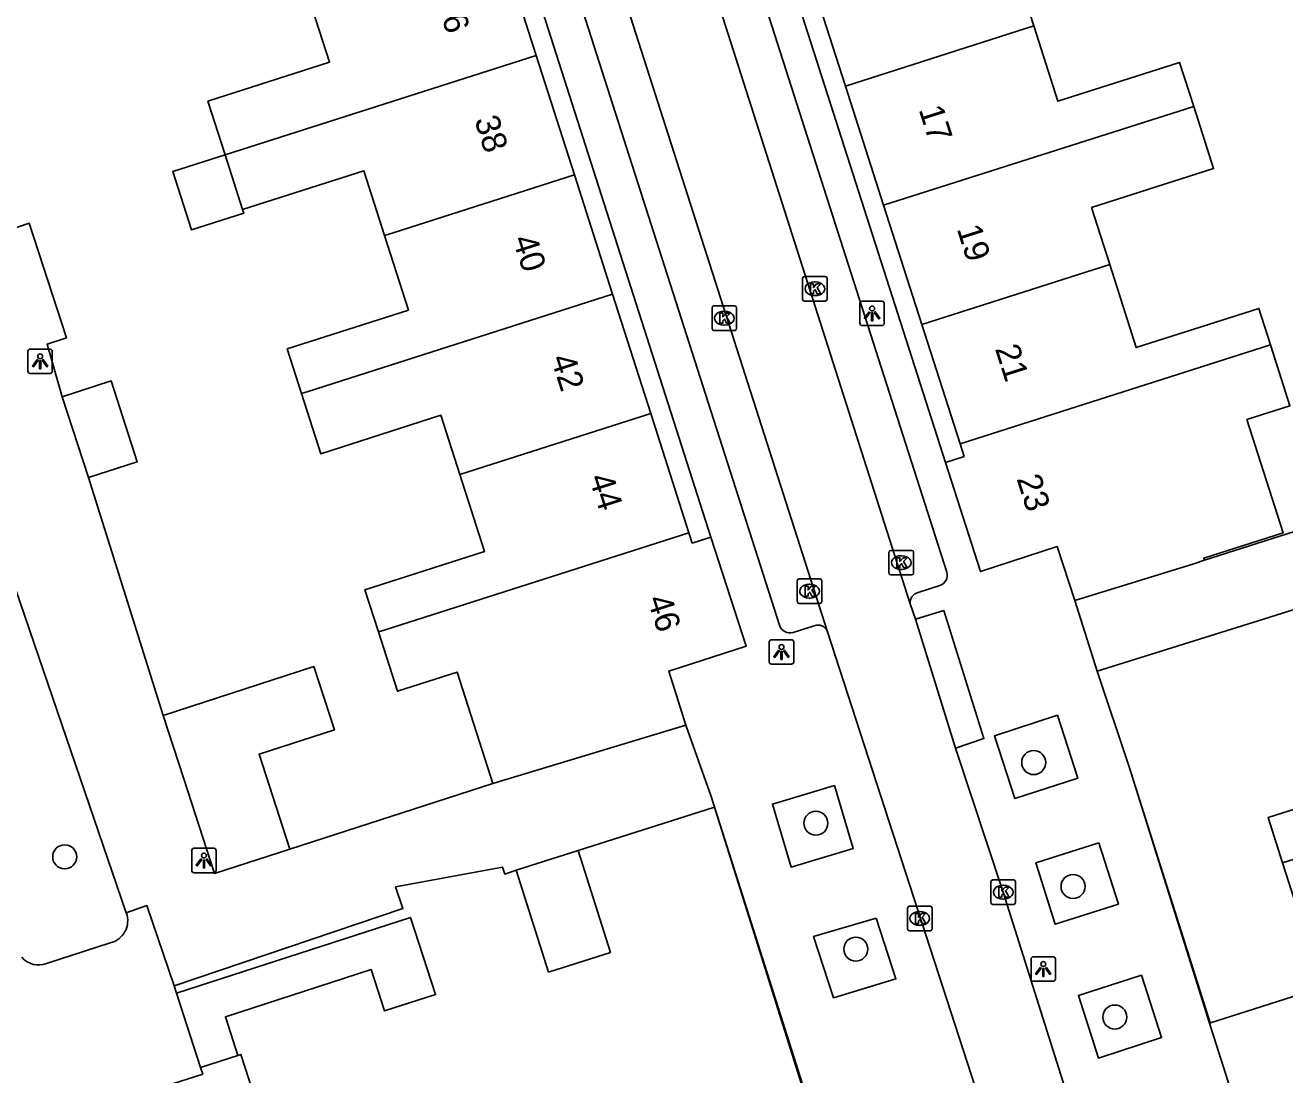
# Model space of a CAD drawing. Extents: x 159718 to 160783, y 383290 to 384030.
# Drawn here: x 160060.5 to 160111.9, y 383577.9 to 383620.7 of the extents above; entities that cross this region are included whole.
import ezdxf

# ---------------------------------------------------------------- set-up
doc = ezdxf.new("R2010")
doc.units = 0
for name, color, linetype in [('IMGEO_Boom', 7, 'Continuous'), ('IMGEO_Kolk', 7, 'Continuous'), ('IMGEO_Lichtpunt', 7, 'Continuous'), ('IMGEO_Muur', 7, 'Continuous'), ('IMGEO_Pand', 7, 'Continuous'), ('IMGEO_Pand_nummerreeks', 7, 'Continuous'), ('IMGEO_Rijbaan_lokaal_open', 7, 'Continuous'), ('IMGEO_Voetpad_open', 7, 'Continuous')]:
    doc.layers.add(name, color=color, linetype=linetype)

msp = doc.modelspace()

# ---------------------------------------------------------------- linework, layer by layer
at = {"layer": 'IMGEO_Boom'}
for centre in [(160101.624, 383590.636), (160092.752, 383588.165), (160062.156, 383586.798), (160103.227, 383585.587), (160094.377, 383583.033), (160104.927, 383580.267)]:
    msp.add_circle(centre, 0.489, dxfattribs=at)
at = {"layer": 'IMGEO_Kolk'}
for p, q in [((160092.21, 383609.519), (160092.21, 383610.371)), ((160092.285, 383610.445), (160093.137, 383610.445)), ((160093.211, 383610.371), (160093.211, 383609.519)), ((160092.698, 383610.225), (160092.723, 383610.225)), ((160093.137, 383609.445), (160092.285, 383609.445)), ((160092.721, 383609.665), (160092.696, 383609.665)), ((160088.522, 383608.32), (160088.522, 383609.172)), ((160088.597, 383609.246), (160089.449, 383609.246)), ((160089.01, 383609.026), (160089.035, 383609.026)), ((160089.523, 383609.172), (160089.523, 383608.32)), ((160089.449, 383608.246), (160088.597, 383608.246)), ((160089.033, 383608.466), (160089.008, 383608.466)), ((160095.73, 383598.359), (160095.73, 383599.211)), ((160095.805, 383599.285), (160096.657, 383599.285)), ((160096.218, 383599.065), (160096.243, 383599.065)), ((160096.731, 383599.211), (160096.731, 383598.359)), ((160096.241, 383598.505), (160096.216, 383598.505)), ((160091.992, 383597.196), (160091.992, 383598.048)), ((160092.067, 383598.122), (160092.919, 383598.122)), ((160092.993, 383598.048), (160092.993, 383597.196)), ((160096.657, 383598.285), (160095.805, 383598.285)), ((160092.48, 383597.902), (160092.505, 383597.902)), ((160092.919, 383597.122), (160092.067, 383597.122)), ((160092.503, 383597.342), (160092.478, 383597.342)), ((160099.883, 383584.928), (160099.883, 383585.78)), ((160099.958, 383585.854), (160100.81, 383585.854)), ((160100.884, 383585.78), (160100.884, 383584.928)), ((160100.371, 383585.634), (160100.396, 383585.634)), ((160096.483, 383583.857), (160096.483, 383584.709)), ((160096.558, 383584.783), (160097.41, 383584.783)), ((160097.484, 383584.709), (160097.484, 383583.857)), ((160100.81, 383584.854), (160099.958, 383584.854)), ((160100.394, 383585.074), (160100.369, 383585.074)), ((160096.971, 383584.563), (160096.996, 383584.563)), ((160097.41, 383583.783), (160096.558, 383583.783)), ((160096.994, 383584.003), (160096.969, 383584.003))]:
    msp.add_line(p, q, dxfattribs=at)
for points in [[(160092.21, 383609.519), (160092.21, 383610.371)], [(160092.285, 383610.445), (160093.137, 383610.445)], [(160093.211, 383610.371), (160093.211, 383609.519)], [(160092.531, 383610.145), (160092.654, 383610.145), (160092.654, 383609.994), (160092.784, 383610.145), (160092.948, 383610.145), (160092.802, 383609.994), (160092.955, 383609.745), (160092.803, 383609.745), (160092.718, 383609.909), (160092.654, 383609.842), (160092.654, 383609.745), (160092.531, 383609.745), (160092.531, 383610.145)], [(160093.137, 383609.445), (160092.285, 383609.445)], [(160088.522, 383608.32), (160088.522, 383609.172)], [(160088.597, 383609.246), (160089.449, 383609.246)], [(160088.843, 383608.946), (160088.966, 383608.946), (160088.966, 383608.795), (160089.096, 383608.946), (160089.26, 383608.946), (160089.114, 383608.795), (160089.267, 383608.546), (160089.115, 383608.546), (160089.03, 383608.71), (160088.966, 383608.643), (160088.966, 383608.546), (160088.843, 383608.546), (160088.843, 383608.946)], [(160089.523, 383609.172), (160089.523, 383608.32)], [(160089.449, 383608.246), (160088.597, 383608.246)], [(160095.73, 383598.359), (160095.73, 383599.211)], [(160095.805, 383599.285), (160096.657, 383599.285)], [(160096.731, 383599.211), (160096.731, 383598.359)], [(160096.051, 383598.985), (160096.174, 383598.985), (160096.174, 383598.834), (160096.304, 383598.985), (160096.468, 383598.985), (160096.322, 383598.834), (160096.475, 383598.585), (160096.323, 383598.585), (160096.238, 383598.749), (160096.174, 383598.682), (160096.174, 383598.585), (160096.051, 383598.585), (160096.051, 383598.985)], [(160091.992, 383597.196), (160091.992, 383598.048)], [(160092.067, 383598.122), (160092.919, 383598.122)], [(160092.993, 383598.048), (160092.993, 383597.196)], [(160096.657, 383598.285), (160095.805, 383598.285)], [(160092.313, 383597.822), (160092.436, 383597.822), (160092.436, 383597.671), (160092.566, 383597.822), (160092.73, 383597.822), (160092.584, 383597.671), (160092.737, 383597.422), (160092.585, 383597.422), (160092.5, 383597.586), (160092.436, 383597.519), (160092.436, 383597.422), (160092.313, 383597.422), (160092.313, 383597.822)], [(160092.919, 383597.122), (160092.067, 383597.122)], [(160099.883, 383584.928), (160099.883, 383585.78)], [(160099.958, 383585.854), (160100.81, 383585.854)], [(160100.884, 383585.78), (160100.884, 383584.928)], [(160100.204, 383585.554), (160100.327, 383585.554), (160100.327, 383585.403), (160100.457, 383585.554), (160100.621, 383585.554), (160100.475, 383585.403), (160100.628, 383585.154), (160100.476, 383585.154), (160100.391, 383585.318), (160100.327, 383585.251), (160100.327, 383585.154), (160100.204, 383585.154), (160100.204, 383585.554)], [(160096.483, 383583.857), (160096.483, 383584.709)], [(160096.558, 383584.783), (160097.41, 383584.783)], [(160097.484, 383584.709), (160097.484, 383583.857)], [(160100.81, 383584.854), (160099.958, 383584.854)], [(160096.804, 383584.483), (160096.927, 383584.483), (160096.927, 383584.332), (160097.057, 383584.483), (160097.221, 383584.483), (160097.075, 383584.332), (160097.228, 383584.083), (160097.076, 383584.083), (160096.991, 383584.247), (160096.927, 383584.18), (160096.927, 383584.083), (160096.804, 383584.083), (160096.804, 383584.483)], [(160097.41, 383583.783), (160096.558, 383583.783)]]:
    msp.add_lwpolyline(points, dxfattribs=at)
for centre, start, end in [((160092.287, 383610.369), 91.552, 178.448), ((160092.287, 383610.369), 91.552, 178.448), ((160093.135, 383610.369), 1.552, 88.448), ((160093.135, 383610.369), 1.552, 88.448), ((160092.287, 383609.521), 181.552, 268.448), ((160092.287, 383609.521), 181.552, 268.448), ((160093.135, 383609.521), 271.552, 358.448), ((160093.135, 383609.521), 271.552, 358.448), ((160088.599, 383609.17), 91.552, 178.448), ((160088.599, 383609.17), 91.552, 178.448), ((160089.447, 383609.17), 1.552, 88.448), ((160089.447, 383609.17), 1.552, 88.448), ((160088.599, 383608.322), 181.552, 268.448), ((160088.599, 383608.322), 181.552, 268.448), ((160089.447, 383608.322), 271.552, 358.448), ((160089.447, 383608.322), 271.552, 358.448), ((160095.807, 383599.209), 91.552, 178.448), ((160095.807, 383599.209), 91.552, 178.448), ((160096.655, 383599.209), 1.552, 88.448), ((160096.655, 383599.209), 1.552, 88.448), ((160092.069, 383598.046), 91.552, 178.448), ((160092.069, 383598.046), 91.552, 178.448), ((160092.917, 383598.046), 1.552, 88.448), ((160092.917, 383598.046), 1.552, 88.448), ((160095.807, 383598.361), 181.552, 268.448), ((160095.807, 383598.361), 181.552, 268.448), ((160096.655, 383598.361), 271.552, 358.448), ((160096.655, 383598.361), 271.552, 358.448), ((160092.069, 383597.198), 181.552, 268.448), ((160092.069, 383597.198), 181.552, 268.448), ((160092.917, 383597.198), 271.552, 358.448), ((160092.917, 383597.198), 271.552, 358.448), ((160099.96, 383585.778), 91.552, 178.448), ((160099.96, 383585.778), 91.552, 178.448), ((160100.808, 383585.778), 1.552, 88.448), ((160100.808, 383585.778), 1.552, 88.448), ((160096.56, 383584.707), 91.552, 178.448), ((160096.56, 383584.707), 91.552, 178.448), ((160097.408, 383584.707), 1.552, 88.448), ((160097.408, 383584.707), 1.552, 88.448), ((160099.96, 383584.93), 181.552, 268.448), ((160099.96, 383584.93), 181.552, 268.448), ((160100.808, 383584.93), 271.552, 358.448), ((160100.808, 383584.93), 271.552, 358.448), ((160096.56, 383583.859), 181.552, 268.448), ((160096.56, 383583.859), 181.552, 268.448), ((160097.408, 383583.859), 271.552, 358.448), ((160097.408, 383583.859), 271.552, 358.448)]:
    msp.add_arc(centre, 0.0765, start, end, dxfattribs=at)
for centre, major_axis, ratio, start_param, end_param in [((160092.697, 383609.945), (-0.387, 0.002), 0.722429, 4.712389, 7.853982), ((160092.722, 383609.945), (-0.39, 0.002), 0.717154, 1.570796, 4.712389), ((160089.009, 383608.746), (-0.387, 0.002), 0.722429, 4.712389, 7.853982), ((160089.034, 383608.746), (-0.39, 0.002), 0.717154, 1.570796, 4.712389), ((160096.217, 383598.785), (-0.387, 0.002), 0.722429, 4.712389, 7.853982), ((160096.242, 383598.785), (-0.39, 0.002), 0.717154, 1.570796, 4.712389), ((160092.479, 383597.622), (-0.387, 0.002), 0.722429, 4.712389, 7.853982), ((160092.504, 383597.622), (-0.39, 0.002), 0.717154, 1.570796, 4.712389), ((160100.37, 383585.354), (-0.387, 0.002), 0.722429, 4.712389, 7.853982), ((160100.395, 383585.354), (-0.39, 0.002), 0.717154, 1.570796, 4.712389), ((160096.97, 383584.283), (-0.387, 0.002), 0.722429, 4.712389, 7.853982), ((160096.995, 383584.283), (-0.39, 0.002), 0.717154, 1.570796, 4.712389)]:
    msp.add_ellipse(centre, major_axis=major_axis, ratio=ratio, start_param=start_param, end_param=end_param, dxfattribs=at)
at = {"layer": 'IMGEO_Lichtpunt'}
for p, q in [((160094.543, 383609.344), (160094.543, 383608.537)), ((160094.543, 383609.344), (160094.543, 383608.537)), ((160095.445, 383609.439), (160094.637, 383609.439)), ((160095.445, 383609.439), (160094.637, 383609.439)), ((160095.539, 383608.537), (160095.539, 383609.344)), ((160095.539, 383608.537), (160095.539, 383609.344)), ((160094.637, 383608.443), (160095.445, 383608.443)), ((160094.637, 383608.443), (160095.445, 383608.443)), ((160060.656, 383607.395), (160060.656, 383606.588)), ((160060.656, 383607.395), (160060.656, 383606.588)), ((160061.558, 383607.49), (160060.75, 383607.49)), ((160061.558, 383607.49), (160060.75, 383607.49)), ((160061.652, 383606.588), (160061.652, 383607.395)), ((160061.652, 383606.588), (160061.652, 383607.395)), ((160060.75, 383606.494), (160061.558, 383606.494)), ((160060.75, 383606.494), (160061.558, 383606.494)), ((160090.852, 383595.548), (160090.852, 383594.741)), ((160090.852, 383595.548), (160090.852, 383594.741)), ((160091.754, 383595.643), (160090.946, 383595.643)), ((160091.754, 383595.643), (160090.946, 383595.643)), ((160091.848, 383594.741), (160091.848, 383595.548)), ((160091.848, 383594.741), (160091.848, 383595.548)), ((160090.946, 383594.647), (160091.754, 383594.647)), ((160090.946, 383594.647), (160091.754, 383594.647)), ((160067.328, 383587.049), (160067.328, 383586.242)), ((160067.328, 383587.049), (160067.328, 383586.242)), ((160068.23, 383587.144), (160067.422, 383587.144)), ((160068.23, 383587.144), (160067.422, 383587.144)), ((160068.324, 383586.242), (160068.324, 383587.049)), ((160068.324, 383586.242), (160068.324, 383587.049)), ((160067.422, 383586.148), (160068.23, 383586.148)), ((160067.422, 383586.148), (160068.23, 383586.148)), ((160101.515, 383582.627), (160101.515, 383581.82)), ((160101.515, 383582.627), (160101.515, 383581.82)), ((160102.417, 383582.722), (160101.609, 383582.722)), ((160102.417, 383582.722), (160101.609, 383582.722)), ((160102.511, 383581.82), (160102.511, 383582.627)), ((160102.511, 383581.82), (160102.511, 383582.627)), ((160101.609, 383581.726), (160102.417, 383581.726)), ((160101.609, 383581.726), (160102.417, 383581.726))]:
    msp.add_line(p, q, dxfattribs=at)
for points in [[(160094.917, 383609.008), (160094.956, 383608.98), (160094.768, 383608.718), (160094.73, 383608.745), (160094.917, 383609.008)], [(160095.019, 383608.96), (160095.066, 383608.96), (160095.066, 383608.638), (160095.019, 383608.638), (160095.019, 383608.96)], [(160095.129, 383608.98), (160095.167, 383609.007), (160095.354, 383608.745), (160095.315, 383608.717), (160095.129, 383608.98)], [(160061.03, 383607.059), (160061.069, 383607.031), (160060.881, 383606.769), (160060.843, 383606.796), (160061.03, 383607.059)], [(160061.132, 383607.011), (160061.179, 383607.011), (160061.179, 383606.689), (160061.132, 383606.689), (160061.132, 383607.011)], [(160061.242, 383607.031), (160061.28, 383607.058), (160061.467, 383606.796), (160061.428, 383606.768), (160061.242, 383607.031)], [(160091.226, 383595.212), (160091.265, 383595.184), (160091.077, 383594.922), (160091.039, 383594.949), (160091.226, 383595.212)], [(160091.328, 383595.164), (160091.375, 383595.164), (160091.375, 383594.842), (160091.328, 383594.842), (160091.328, 383595.164)], [(160091.438, 383595.184), (160091.476, 383595.211), (160091.663, 383594.949), (160091.624, 383594.921), (160091.438, 383595.184)], [(160067.702, 383586.713), (160067.741, 383586.685), (160067.553, 383586.423), (160067.515, 383586.45), (160067.702, 383586.713)], [(160067.914, 383586.685), (160067.952, 383586.712), (160068.139, 383586.45), (160068.1, 383586.422), (160067.914, 383586.685)], [(160067.804, 383586.665), (160067.851, 383586.665), (160067.851, 383586.343), (160067.804, 383586.343), (160067.804, 383586.665)], [(160101.889, 383582.291), (160101.928, 383582.263), (160101.74, 383582.001), (160101.702, 383582.028), (160101.889, 383582.291)], [(160101.991, 383582.243), (160102.038, 383582.243), (160102.038, 383581.921), (160101.991, 383581.921), (160101.991, 383582.243)], [(160102.101, 383582.263), (160102.139, 383582.29), (160102.326, 383582.028), (160102.287, 383582), (160102.101, 383582.263)]]:
    msp.add_lwpolyline(points, dxfattribs=at)
for centre in [(160095.042, 383609.142), (160061.155, 383607.193), (160091.351, 383595.346), (160067.827, 383586.847), (160102.014, 383582.425)]:
    msp.add_circle(centre, 0.0994, dxfattribs=at)
for centre, start, end in [((160094.637, 383609.344), 90, 180), ((160094.637, 383609.344), 90, 180), ((160095.445, 383609.344), 0, 90), ((160095.445, 383609.344), 0, 90), ((160094.637, 383608.537), 180, 270), ((160094.637, 383608.537), 180, 270), ((160095.445, 383608.537), 270, 0), ((160095.445, 383608.537), 270, 360), ((160060.75, 383607.395), 90, 180), ((160060.75, 383607.395), 90, 180), ((160061.558, 383607.395), 0, 90), ((160061.558, 383607.395), 0, 90), ((160060.75, 383606.588), 180, 270), ((160060.75, 383606.588), 180, 270), ((160061.558, 383606.588), 270, 0), ((160061.558, 383606.588), 270, 360), ((160090.946, 383595.548), 90, 180), ((160090.946, 383595.548), 90, 180), ((160091.754, 383595.548), 0, 90), ((160091.754, 383595.548), 0, 90), ((160090.946, 383594.741), 180, 270), ((160090.946, 383594.741), 180, 270), ((160091.754, 383594.741), 270, 0), ((160091.754, 383594.741), 270, 360), ((160067.422, 383587.049), 90, 180), ((160067.422, 383587.049), 90, 180), ((160068.23, 383587.049), 0, 90), ((160068.23, 383587.049), 0, 90), ((160067.422, 383586.242), 180, 270), ((160067.422, 383586.242), 180, 270), ((160068.23, 383586.242), 270, 0), ((160068.23, 383586.242), 270, 360), ((160101.609, 383582.627), 90, 180), ((160101.609, 383582.627), 90, 180), ((160102.417, 383582.627), 0, 90), ((160102.417, 383582.627), 0, 90), ((160101.609, 383581.82), 180, 270), ((160101.609, 383581.82), 180, 270), ((160102.417, 383581.82), 270, 0), ((160102.417, 383581.82), 270, 360)]:
    msp.add_arc(centre, 0.0946, start, end, dxfattribs=at)
at = {"layer": 'IMGEO_Muur'}
for points in [[(160108.81, 383580.026), (160105.518, 383590.459)], [(160093.03, 383574.919), (160088.483, 383589.256)]]:
    msp.add_lwpolyline(points, dxfattribs=at)
at = {"layer": 'IMGEO_Pand'}
for points in [[(160101.626, 383620.655), (160100.765, 383623.356), (160105.761, 383624.949), (160105.071, 383627.111)], [(160081.362, 383619.454), (160079.807, 383624.317)], [(160092.396, 383623.068), (160093.953, 383618.208)], [(160068.687, 383615.399), (160067.986, 383617.59), (160072.943, 383619.176), (160072.088, 383621.848)], [(160093.953, 383618.208), (160101.626, 383620.655)], [(160108.141, 383617.377), (160107.568, 383619.172), (160102.604, 383617.589), (160101.626, 383620.655)], [(160081.362, 383619.454), (160068.687, 383615.399)], [(160082.917, 383614.592), (160081.362, 383619.454)], [(160093.953, 383618.208), (160095.51, 383613.348)], [(160108.141, 383617.377), (160095.51, 383613.348)], [(160104.722, 383610.928), (160103.979, 383613.257), (160108.949, 383614.842), (160108.141, 383617.377)], [(160069.399, 383613.174), (160069.447, 383613.024), (160067.317, 383612.342), (160066.557, 383614.718), (160068.687, 383615.399)], [(160068.687, 383615.399), (160069.399, 383613.174)], [(160069.399, 383613.174), (160074.338, 383614.754), (160075.182, 383612.117)], [(160075.182, 383612.117), (160075.538, 383612.231), (160082.917, 383614.592)], [(160084.471, 383609.73), (160082.917, 383614.592)], [(160095.51, 383613.348), (160097.067, 383608.487)], [(160075.182, 383612.117), (160076.154, 383609.079), (160071.22, 383607.5), (160071.803, 383605.677)], [(160097.067, 383608.487), (160104.722, 383610.928)], [(160111.27, 383607.66), (160110.797, 383609.145), (160105.799, 383607.551), (160104.722, 383610.928)], [(160084.471, 383609.73), (160072.069, 383605.762), (160071.803, 383605.677)], [(160086.026, 383604.867), (160084.471, 383609.73)], [(160097.067, 383608.487), (160098.624, 383603.627)], [(160098.624, 383603.627), (160111.27, 383607.66)], [(160108.575, 383598.879), (160108.547, 383598.968), (160111.782, 383600), (160110.311, 383604.614), (160112.063, 383605.173), (160111.27, 383607.66)], [(160062.055, 383605.547), (160064.047, 383606.191), (160065.113, 383602.894), (160063.121, 383602.25)], [(160071.803, 383605.677), (160072.587, 383603.224), (160077.482, 383604.79), (160078.253, 383602.38)], [(160063.121, 383602.25), (160062.055, 383605.547)], [(160078.253, 383602.38), (160078.593, 383602.489), (160086.026, 383604.867)], [(160087.582, 383600.004), (160086.026, 383604.867)], [(160098.624, 383603.627), (160098.789, 383603.111), (160098.028, 383602.867)], [(160098.028, 383602.867), (160099.456, 383598.422), (160102.586, 383599.437), (160103.294, 383597.238)], [(160074.935, 383595.959), (160074.385, 383597.68), (160079.258, 383599.239), (160078.253, 383602.38)], [(160087.582, 383600.004), (160075.169, 383596.034), (160074.935, 383595.959)], [(160088.478, 383599.828), (160089.909, 383595.376), (160086.757, 383594.365), (160087.46, 383592.162)], [(160088.478, 383599.828), (160087.716, 383599.583), (160087.582, 383600.004)], [(160108.575, 383598.879), (160108.146, 383598.742), (160103.294, 383597.238)], [(160079.595, 383589.79), (160078.145, 383594.326), (160075.707, 383593.546), (160074.935, 383595.959)], [(160066.171, 383592.559), (160072.307, 383594.545), (160073.142, 383591.966), (160070.074, 383590.973), (160071.326, 383587.105)], [(160071.326, 383587.105), (160068.258, 383586.111), (160067.006, 383589.979), (160066.171, 383592.559)], [(160087.46, 383592.162), (160079.595, 383589.79)], [(160111.764, 383586.547), (160111.173, 383588.394), (160113.104, 383589.012), (160113.694, 383587.165)], [(160080.549, 383586.253), (160083.064, 383587.057)], [(160083.064, 383587.057), (160084.382, 383582.901), (160081.867, 383582.097), (160080.549, 383586.253)], [(160113.694, 383587.165), (160111.764, 383586.547)], [(160108.784, 383580.014), (160113.382, 383581.489), (160111.764, 383586.547)], [(160066.713, 383581.238), (160076.247, 383584.326), (160077.263, 383581.188), (160075.18, 383580.514), (160074.634, 383582.2), (160068.702, 383580.28), (160069.212, 383578.705)], [(160066.713, 383581.238), (160067.693, 383578.213)], [(160108.784, 383580.014), (160110.383, 383574.974)], [(160067.693, 383578.213), (160069.212, 383578.705)], [(160069.212, 383578.705), (160069.327, 383578.742), (160072.068, 383570.277), (160070.582, 383569.796)], [(160067.693, 383578.213), (160067.782, 383577.939), (160066.245, 383577.442)]]:
    msp.add_lwpolyline(points, dxfattribs=at)
at = {"layer": 'IMGEO_Rijbaan_lokaal_open'}
for points in [[(160096.587, 383597.112), (160087.826, 383624.591)], [(160084.42, 383623.496), (160093.206, 383595.999)], [(160096.587, 383597.112), (160096.806, 383596.486)], [(160098.433, 383591.22), (160096.806, 383596.486)], [(160100.43, 383573.741), (160093.206, 383595.999)], [(160098.433, 383591.22), (160100.384, 383585.354), (160104.021, 383573.815)]]:
    msp.add_lwpolyline(points, dxfattribs=at)
at = {"layer": 'IMGEO_Voetpad_open'}
for points in [[(160079.624, 383656.083), (160098.092, 383598.396)], [(160091.264, 383596.231), (160072.804, 383653.926)], [(160082.144, 383652.447), (160098.028, 383602.867)], [(160072.621, 383649.414), (160088.478, 383599.828)], [(160104.211, 383594.364), (160110.764, 383596.41), (160127.456, 383601.679), (160120.476, 383623.696), (160119.09, 383628.068), (160113.81, 383644.725), (160123.842, 383647.93)], [(160115.198, 383635.752), (160121.604, 383615.913), (160125.373, 383604.243), (160108.575, 383598.879)], [(160062.055, 383605.547), (160061.437, 383607.691), (160062.226, 383607.946), (160060.714, 383612.62), (160059.874, 383612.332)], [(160056.648, 383611.226), (160055.644, 383610.877), (160064.665, 383584.508)], [(160066.171, 383592.559), (160063.121, 383602.25)], [(160097.796, 383597.855), (160096.924, 383597.571)], [(160103.294, 383597.238), (160104.211, 383594.364)], [(160096.806, 383596.486), (160097.962, 383596.832), (160099.593, 383591.624), (160098.433, 383591.22)], [(160092.689, 383596.206), (160091.827, 383595.933)], [(160104.211, 383594.364), (160105.518, 383590.459), (160108.784, 383580.014)], [(160102.599, 383592.562), (160103.427, 383590.003), (160100.858, 383589.172), (160100.03, 383591.731), (160102.599, 383592.562)], [(160087.46, 383592.162), (160088.483, 383589.256), (160088.621, 383588.82)], [(160079.595, 383589.79), (160071.326, 383587.105)], [(160093.506, 383589.699), (160094.272, 383587.135), (160091.746, 383586.38), (160090.98, 383588.944), (160093.506, 383589.699)], [(160083.064, 383587.057), (160088.621, 383588.82)], [(160088.621, 383588.82), (160092.964, 383574.977)], [(160104.283, 383587.369), (160105.075, 383584.861), (160102.501, 383584.048), (160101.708, 383586.556), (160104.283, 383587.369)], [(160066.615, 383581.531), (160075.935, 383584.689), (160075.634, 383585.576), (160079.988, 383586.376), (160080.083, 383586.095), (160080.549, 383586.253)], [(160064.665, 383584.508), (160065.501, 383584.818), (160066.615, 383581.531)], [(160095.202, 383584.296), (160096.013, 383581.82), (160093.463, 383581.051), (160092.658, 383583.548), (160095.202, 383584.296)], [(160064.009, 383583.284), (160061.419, 383582.447)], [(160106.01, 383581.974), (160106.836, 383579.429), (160104.268, 383578.595), (160103.442, 383581.139), (160106.01, 383581.974)], [(160066.615, 383581.531), (160066.713, 383581.238)]]:
    msp.add_lwpolyline(points, dxfattribs=at)
for centre, radius, start, end in [((160097.66, 383598.281), 0.447, 287.7226, 14.9082), ((160097.039, 383597.134), 0.452, 104.6832, 182.7442), ((160091.711, 383596.394), 0.476, 200.0787, 284.1361), ((160092.849, 383595.856), 0.385, 21.8561, 114.5029), ((160063.794, 383584.187), 0.928, 283.378, 20.2441), ((160061.095, 383583.285), 0.899, 220.4555, 291.1513)]:
    msp.add_arc(centre, radius, start, end, dxfattribs=at)

# ---------------------------------------------------------------- texts
at = {"layer": 'IMGEO_Pand_nummerreeks'}
for s, rotation, p in [('36', 287.7386, (160077.278, 383621.694)), ('38', 287.7386, (160078.834, 383616.829)), ('17', 287.687, (160096.934, 383617.253)), ('19', 287.687, (160098.485, 383612.391)), ('40', 287.7386, (160080.39, 383611.967)), ('21', 287.687, (160100.041, 383607.507)), ('42', 287.7386, (160081.943, 383607.111)), ('44', 287.7386, (160083.5, 383602.245)), ('23', 287.6927, (160100.919, 383602.208)), ('46', 287.7443, (160085.876, 383597.295))]:
    msp.add_text(s, height=1, rotation=rotation, dxfattribs=at).set_placement(p)

doc.saveas('drawing.dxf')
